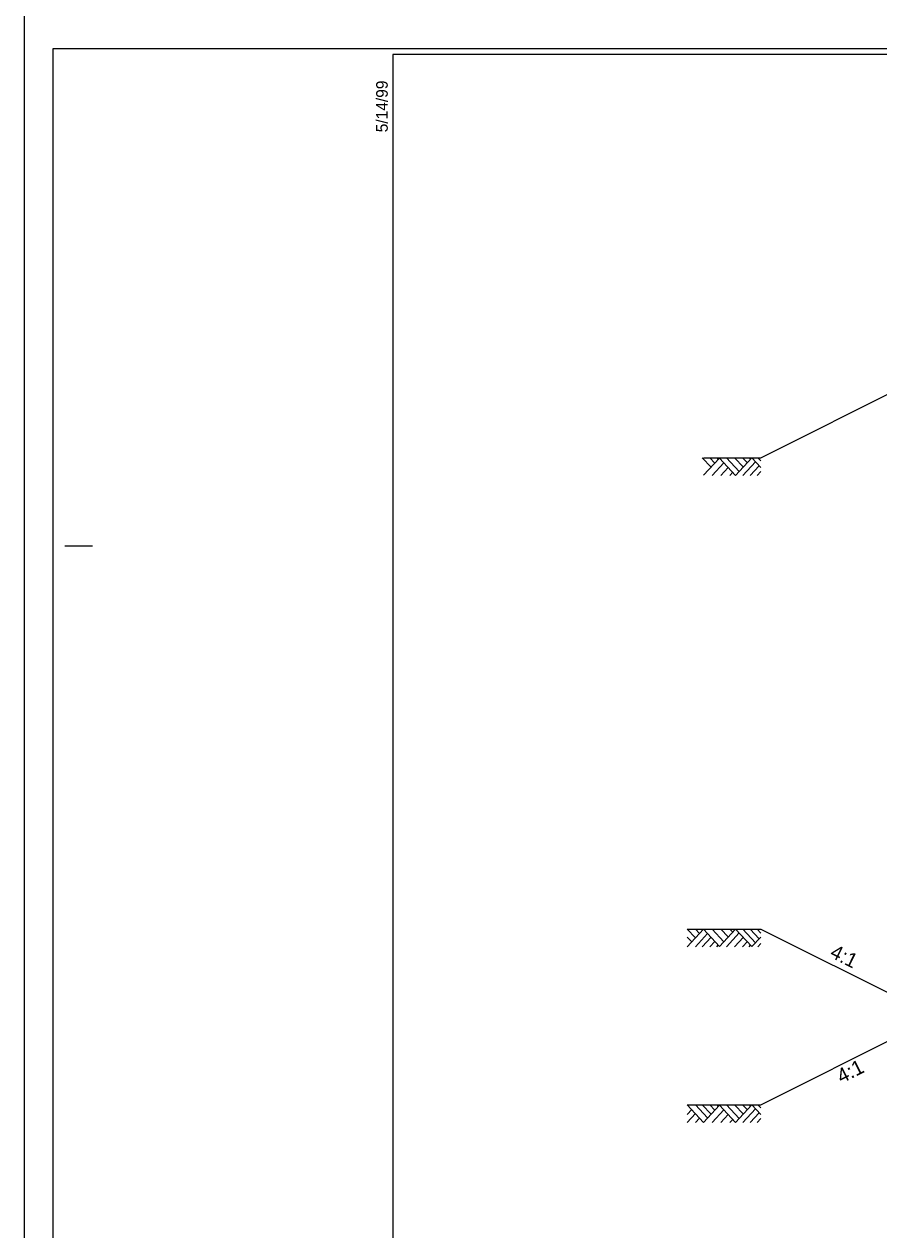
# Model space of a CAD drawing. Extents: x 1901670 to 1902225, y 193498 to 194278.
# Drawn here: x 1901965.8 to 1902004.6, y 193992.3 to 194046.9 of the extents above; entities that cross this region are included whole.
import ezdxf

# ---------------------------------------------------------------- set-up
doc = ezdxf.new("R2010")
doc.units = 0
for name, color, linetype in [('Old_Level_1', 7, 'Continuous'), ('Sheet Border Standard 30in CELL', 7, 'Continuous'), ('Sheet Cutting Line CELL', 7, 'Continuous'), ('Sheet Plot Border Inside CELL', 7, 'Continuous'), ('Sheet Plot Border Outside CELL', 7, 'Continuous'), ('Typical Pavement Slope CELL', 7, 'Continuous')]:
    doc.layers.add(name, color=color, linetype=linetype)

msp = doc.modelspace()

# ---------------------------------------------------------------- linework, layer by layer
at = {"layer": 'Old_Level_1'}
for p, q in [((1901999.227, 194027.259), (1902007.184, 194031.238)), ((1901996.568, 194027.259), (1901996.969, 194026.83)), ((1901996.627, 194026.462), (1901997.351, 194027.241)), ((1901996.915, 194027.259), (1901997.142, 194027.016)), ((1901997.226, 194027.259), (1901997.297, 194027.183)), ((1901997.351, 194027.241), (1901998.082, 194026.455)), ((1901997.661, 194027.259), (1901998.247, 194026.631)), ((1901998.031, 194027.259), (1901998.431, 194026.83)), ((1901998.082, 194026.455), (1901998.823, 194027.251)), ((1901998.397, 194027.259), (1901998.614, 194027.026)), ((1901998.404, 194026.454), (1901998.984, 194027.077)), ((1901998.692, 194027.259), (1901998.761, 194027.185)), ((1901998.823, 194027.251), (1901999.227, 194026.816)), ((1901999.093, 194027.259), (1901999.227, 194027.116)), ((1901997.018, 194026.454), (1901997.551, 194027.027)), ((1901997.416, 194026.454), (1901997.749, 194026.813)), ((1901997.818, 194026.454), (1901997.951, 194026.597)), ((1901998.737, 194026.454), (1901999.151, 194026.898)), ((1901999.057, 194026.454), (1901999.227, 194026.637)), ((1901995.885, 194005.917), (1901996.26, 194005.514)), ((1901995.885, 194005.112), (1901996.627, 194005.909)), ((1901996.26, 194005.917), (1901996.447, 194005.716)), ((1901996.627, 194005.909), (1901997.351, 194005.13)), ((1901997.018, 194005.917), (1901997.551, 194005.344)), ((1901997.351, 194005.13), (1901998.082, 194005.916)), ((1901997.416, 194005.917), (1901997.749, 194005.558)), ((1901997.818, 194005.917), (1901997.951, 194005.774)), ((1901998.082, 194005.916), (1901998.823, 194005.12)), ((1901998.404, 194005.917), (1901998.984, 194005.294)), ((1901998.737, 194005.917), (1901999.151, 194005.473)), ((1901999.057, 194005.917), (1901999.227, 194005.734)), ((1901995.885, 194005.555), (1901996.091, 194005.333)), ((1901996.259, 194005.112), (1901996.813, 194005.708)), ((1901996.568, 194005.112), (1901996.969, 194005.541)), ((1901996.915, 194005.112), (1901997.142, 194005.355)), ((1901997.661, 194005.112), (1901998.247, 194005.74)), ((1901998.031, 194005.112), (1901998.431, 194005.541)), ((1901998.397, 194005.112), (1901998.614, 194005.345)), ((1901998.823, 194005.12), (1901999.227, 194005.555)), ((1901999.093, 194005.112), (1901999.227, 194005.255)), ((1901997.226, 194005.112), (1901997.297, 194005.188)), ((1901998.692, 194005.112), (1901998.761, 194005.186)), ((1901995.885, 193997.96), (1901996.627, 193997.163)), ((1901995.885, 193997.517), (1901996.091, 193997.739)), ((1901995.885, 193997.155), (1901996.26, 193997.558)), ((1901996.259, 193997.96), (1901996.813, 193997.364)), ((1901996.568, 193997.96), (1901996.969, 193997.531)), ((1901996.627, 193997.163), (1901997.351, 193997.942)), ((1901996.915, 193997.96), (1901997.142, 193997.717)), ((1901997.018, 193997.155), (1901997.551, 193997.728)), ((1901997.226, 193997.96), (1901997.297, 193997.884)), ((1901997.351, 193997.942), (1901998.082, 193997.156)), ((1901997.661, 193997.96), (1901998.247, 193997.332)), ((1901998.031, 193997.96), (1901998.431, 193997.531)), ((1901998.082, 193997.156), (1901998.823, 193997.952)), ((1901998.397, 193997.96), (1901998.614, 193997.727)), ((1901998.404, 193997.155), (1901998.984, 193997.778)), ((1901998.692, 193997.96), (1901998.761, 193997.886)), ((1901998.737, 193997.155), (1901999.151, 193997.599)), ((1901998.823, 193997.952), (1901999.227, 193997.517)), ((1901999.093, 193997.96), (1901999.227, 193997.817)), ((1901996.26, 193997.155), (1901996.447, 193997.356)), ((1901997.416, 193997.155), (1901997.749, 193997.514)), ((1901997.818, 193997.155), (1901997.951, 193997.298)), ((1901999.057, 193997.155), (1901999.227, 193997.338))]:
    msp.add_line(p, q, dxfattribs=at)
msp.add_lwpolyline([(1901996.627, 194027.259), (1901999.227, 194027.259)], dxfattribs=at)
at = {"layer": 'Sheet Border Standard 30in CELL'}
for p, q in [((1901982.644, 194045.514), (1901982.644, 194045.514)), ((1901967.694, 194023.264), (1901968.944, 194023.264))]:
    msp.add_line(p, q, dxfattribs=at)
msp.add_lwpolyline([(1902132.544, 194045.514), (1901982.544, 194045.514), (1901982.544, 193940.514), (1902132.544, 193940.514)], close=True, dxfattribs=at)
at = {"layer": 'Sheet Cutting Line CELL'}
msp.add_line((1901965.844, 194048.014), (1901965.844, 193938.014), dxfattribs=at)
at = {"layer": 'Sheet Plot Border Inside CELL'}
msp.add_lwpolyline([(1902133.794, 194045.769), (1901967.144, 194045.769), (1901967.144, 193940.259), (1902133.794, 193940.259)], close=True, dxfattribs=at)
at = {"layer": 'Sheet Plot Border Outside CELL'}
msp.add_lwpolyline([(1902134.244, 194048.014), (1901965.844, 194048.014), (1901965.844, 193938.014), (1902134.244, 193938.014)], close=True, dxfattribs=at)
at = {"layer": 'Typical Pavement Slope CELL'}
for p in [(1901999.227, 194005.917), (1901999.227, 193997.96)]:
    msp.add_line(p, (1902007.184, 194001.939), dxfattribs=at)
for points in [[(1901995.885, 194005.917), (1901999.227, 194005.917)], [(1901995.885, 193997.96), (1901999.227, 193997.96)]]:
    msp.add_lwpolyline(points, dxfattribs=at)

# ---------------------------------------------------------------- texts
at = {"layer": 'Old_Level_1'}
for rotation, p in [(333.4349, (1902002.309, 194004.666)), (26.5651, (1902002.875, 193998.911))]:
    msp.add_text('4:1', height=0.656, rotation=rotation, dxfattribs=at).set_placement(p)
at = {"layer": 'Sheet Border Standard 30in CELL'}
msp.add_text('5/14/99', height=0.525, rotation=90, dxfattribs=at).set_placement((1901982.319, 194041.994))

doc.saveas('drawing.dxf')
